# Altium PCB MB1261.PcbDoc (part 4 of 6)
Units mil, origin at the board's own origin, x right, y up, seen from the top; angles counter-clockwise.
Board outline 5119.1 x 2638.79 mil, 6 copper layers (TOP, L2_GND, L3_SIG, L4_VCC, L5_GND, BOTTOM), stack 61 mil thick; 336 components, 316 nets, 1358 pads, 871 vias.
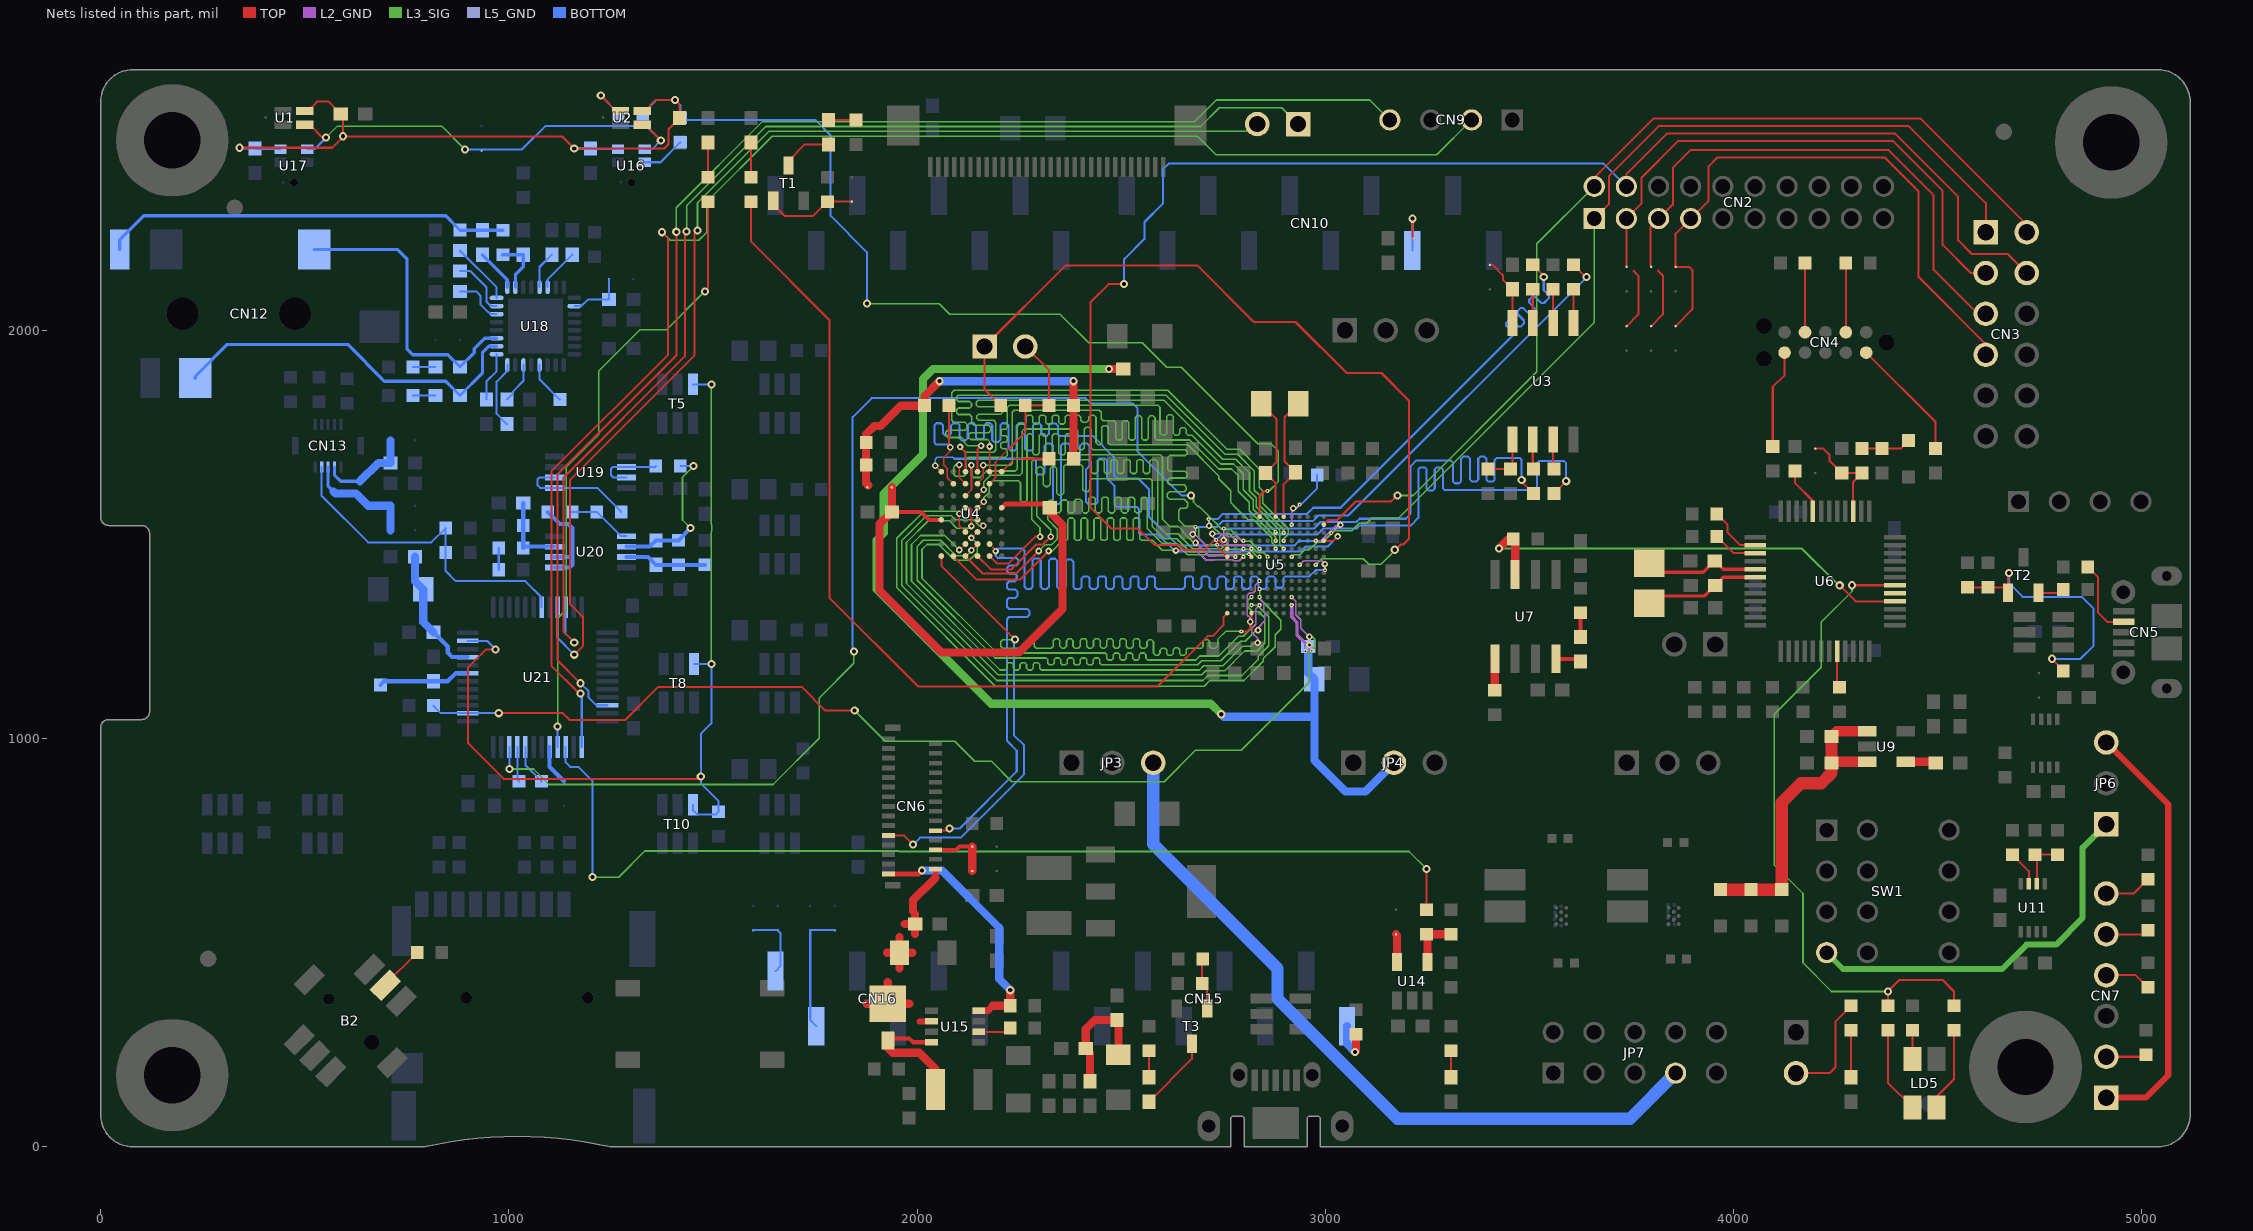
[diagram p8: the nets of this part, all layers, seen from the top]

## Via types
v1: diameter 20, hole 10, TOP to BOTTOM, tented both sides, 317 vias
v2: diameter 24, hole 12, TOP to BOTTOM, tented both sides, 289 vias
v3: diameter 10, hole 4, TOP to L2_GND, tented both sides, 76 vias
v4: diameter 10, hole 4, TOP to L3_SIG, tented both sides, 63 vias
v5: diameter 16, hole 8, L2_GND to L5_GND, tented both sides, 52 vias
v6: diameter 16, hole 8, TOP to BOTTOM, tented both sides, 43 vias
v7: diameter 10, hole 4, L5_GND to BOTTOM, tented both sides, 31 vias

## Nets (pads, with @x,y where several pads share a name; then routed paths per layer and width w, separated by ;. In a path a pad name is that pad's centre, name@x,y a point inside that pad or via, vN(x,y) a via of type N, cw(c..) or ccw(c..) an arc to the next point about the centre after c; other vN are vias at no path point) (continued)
LCD_WE: CN6.20 U4.G5 U5.D7 | length 3052.1
  TOP w4: U4.G5@2177.39,1476.18 2191.55,1462.02 2191.55,1459.25 v6(2192.05,1458.75)
  TOP w5: CN6.20@2044.44,774.27 2074.5,774.27 v1(2079.5,779.27)
  L2_GND w3.5: v3(2937.16,1425) 2947.1,1434.94 2991.06,1434.94 v5(2999,1427)
  L5_GND w3.5: v7(2999,1412) v5(2999,1427)
  BOTTOM w5: v1(2079.5,779.27) 2104.27,779.27 2244,919 2244,970 2220,994 2220,1292.32 2225,1297.32 2270,1297.32 2275,1302.32 2275,1312.32 2270,1317.32 2225,1317.32 2220,1322.32 2220,1339.32 2225,1344.32 2241,1344.32 2246,1349.32 2246,1359.32 2241,1364.32 2225,1364.32 2220,1369.32 2220,1379.32 2225,1384.32 2239,1384.32 2244,1389.32 2244,1399.32 2239,1404.32 2225,1404.32 2220,1409.32 2220,1418 2225,1423 2243,1423 2248,1428 2248,1437 2243,1442 2197.05,1442 2192.05,1447 v6(2192.05,1458.75) 2198.3,1465 2258,1465 2263,1460 2263,1371 2268,1366 2277.75,1366 2282.75,1371 2282.75,1436 2287.75,1441 2297.75,1441 2302.75,1436 2302.75,1371 2307.75,1366 2317.75,1366 2322.75,1371 2322.75,1435 2327.75,1440 2337.75,1440 2342.75,1435 2342.75,1371 2347.75,1366 2357.75,1366 2362.75,1371 2362.75,1433 2367.75,1438 2377.75,1438 2382.75,1433 2382.75,1371 2387.75,1366 2397.75,1366 2402.75,1371 2402.75,1392 2407.75,1397 2417.75,1397 2422.75,1392 2422.75,1371 2427.75,1366 2437.75,1366 2442.75,1371 2442.75,1392 2447.75,1397 2457.75,1397 2462.75,1392 2462.75,1371 2467.75,1366 2477.75,1366 2482.75,1371 2482.75,1392 2487.75,1397 2497.75,1397 2502.75,1392 2502.75,1371 2507.75,1366 2517.75,1366 2522.75,1371 2522.75,1392 2527.75,1397 2537.75,1397 2542.75,1392 2542.75,1371 2547.75,1366 2557.75,1366 2562.75,1371 2562.75,1392 2567.75,1397 2577.75,1397 2582.75,1392 2582.75,1371 2587.75,1366 2651.06,1366 2656.06,1371 2656.06,1392 2661.06,1397 2671.06,1397 2676.06,1392 2676.06,1371 2681.06,1366 2691.06,1366 2696.06,1371 2696.06,1392 2701.06,1397 2711.06,1397 2716.06,1392 2716.06,1371 2721.06,1366 2731.06,1366 2736.06,1371 2736.06,1392 2741.06,1397 2751.06,1397 2756.06,1392 2756.06,1371 2761.06,1366 2771.06,1366 2776.06,1371 2776.06,1392 2781.06,1397 2791.06,1397 2796.06,1392 2796.06,1371 2801.06,1366 2811.06,1366 2816.06,1371 2816.06,1392 2821.06,1397 2831.06,1397 2836.06,1392 2836.06,1371 2841.06,1366 2851.06,1366 2856.06,1371 2856.06,1392 2861.06,1397 2872.34,1397 2877.34,1392 2877.34,1374 2882.34,1369 2892.34,1369 2897.34,1374 2897.34,1392 2902.34,1397 2961,1397 2976,1412 v7(2999,1412)
LED1: R2.1 U5.N13 | length 2201.1
  TOP w5: R2.1@1593.1,2315 1593.1,2216.9 1785,2025 1785,1345 2003,1127 2588.22,1127 2711.72,1250.5 2723.72,1250.5 2750,1276.78 2750,1296.9 U5.N13@2759.99,1306.89
LED_STLINK: R69.1 R71.1 U6.30 | length 1630.4
  TOP w5: v1(4290,1375.16) U6.30@4395.36,1375.16 ; R69.1@4378.1,345 v1(4378.1,380) 4406.1,408 4512,408 4540,380 R71.1@4540,345
  L3_SIG w4: v1(4290,1375.16) 4290,1360 4215,1285 4215,1174 4100,1059 4100,690 4170,620 4170,450 4240,380 v1(4378.1,380)
LEDA: C47.1 C48.1 CN6.28 U15.6 Z1.2 | length 523.8
  TOP w12: 2044.44,658.44 CN6.28@2044.44,679.79
  TOP w15: 2006.3,306.8 U15.6@2035.03,306.8
  TOP w20: 1875.58,350 Z1.2@1928.1,350 ; 1925.98,475 C48.1@1957,475 ; 1928.1,403.02 Z1.2@1928.1,350 ; 1957,436.98 C48.1@1957,475 ; 1957,513.02 C48.1@1957,475 ; 1969.48,545 C47.1@1995,545 ; 1980.62,350 Z1.2@1928.1,350 ; 1988.02,475 C48.1@1957,475 ; 1990,577 1990,604 2044.44,658.44 ; 1995,520.98 C47.1@1995,545 ; 1995,569.02 C47.1@1995,545
LEDK: CN6.29 R67.1 U15.4 | length 616.4
  TOP w12: CN6.29@1930.26,667.98 2003.98,667.98 v1(2012,676)
  TOP w16: U15.4@2151.17,332.39 2172.39,332.39 2185,345
  TOP w20: 2185,345 R67.1@2228.1,345 v1(2228.1,383.1)
  BOTTOM w20: v1(2012,676) 2061,676 2201,536 2201,410.2 v1(2228.1,383.1)
MCO: U6.29
MFX_AGPIO1: R116.1 T5.3 T8.3 T10.3 U21.11 | length 2204.1
  TOP w5: v1(967,1218) 944,1218 900,1174 900,988 987,901 1464,901 v1(1470,907)
  L3_SIG w4: v1(1496,1182.24) 1496,1507.45 1497,1508.45 1497,1522.55 1496,1523.55 v1(1496,1867.24)
  BOTTOM w5: U21.11@898.74,1238.58 946.42,1238.58 v1(967,1218) ; T10.3@1450.5,837.24 1450.5,824.5 1462,813 1506.1,813 R116.1@1513.1,820 1513.1,846.9 1470,890 v1(1470,907) 1470,1011 1496,1037 v1(1496,1182.24) T8.3@1453.6,1182.24 ; T5.3@1450.5,1867.24 v1(1496,1867.24)
MFX_IRQ_OUT: U5.J5 U21.46 | length 2936
  L3_SIG w3.5: 2730,1529 2748,1511 2768,1511 2796,1483 2815.97,1483 2832.16,1466.81 ; 2832.19,1466.81 2834.63,1464.37 v4(2838.73,1464.37)
  L3_SIG w4: v1(1001.1,925) 1060,925 1098,887 1647,887 1760,1000 1760,1099 1845,1184 v1(1845,1213) ; v1(2670.71,1595.11) 2672,1595.11 2677,1590.11 2677,1578.95 2686.95,1569 ; 2687,1569 2688,1568 2691,1568 2730,1529
  BOTTOM w5: v1(1001.1,925) U21.46@1001.1,978.74 ; v1(1845,1213) 1841.88,1216.12 1841.88,1786.88 1888.34,1833.34 2412.29,1833.34 2425,1820.63 2527.63,1820.63 2540.01,1808.25 2540.01,1702.43 2647.33,1595.11 v1(2670.71,1595.11)
MFX_SWCLK: CN9.2 U21.37 | length 3613.2
  TOP w5: v1(1175,1110) 1172,1110 1104,1178 1104,1654 1390,1940 1390,2225 v1(1375,2240)
  L3_SIG w4: v1(1375,2240) 1395,2220 1465,2220 1485,2240 1485,2315 1645,2475 2687,2475 2732,2430 3273.1,2430 CN9.2@3358.1,2515
  BOTTOM w5: v1(1175,1110) 1178.27,1106.73 U21.37@1178.27,978.74
MFX_SWDIO: CN9.4 U21.34 | length 3283.9
  TOP w5: v1(1175,1135) 1119,1191 1119,1647 1410,1938 v1(1410,2241)
  L3_SIG w4: v1(1410,2241) 1410,2300 1621,2511 2680,2511 2733,2564 3109.1,2564 CN9.4@3158.1,2515
  BOTTOM w5: v1(1175,1135) 1195,1115 1195,1100 1213.9,1081.1 U21.34@1241.26,1081.1
MFX_WAKEUP: R109.2 U5.E11 U21.2 | length 2632.4
  TOP w5: v1(975,1061.73) 1132.05,1061.73 1148.78,1045 1285,1045 1366,1126 1717,1126 1775,1068 v1(1847,1068)
  L2_GND w3.5: v3(2917.47,1346.26) 2927.22,1336.51 2927.22,1302.78 2940,1290 2940,1270 v5(2961,1249)
  L3_SIG w3.5: 2959.5,1208.5 2973.75,1222.75 2973.75,1242.94 2967.69,1249 v5(2961,1249)
  L3_SIG w4: v1(1847,1068) 1922,993 2092,993 2141,944 2182,944 2232,894 2605,894 2682,971 2794,971 2959.5,1136.5 2959.5,1208.5
  BOTTOM w5: R109.2@815,1080 833.27,1061.73 U21.2@898.43,1061.73 ; U21.2@898.74,1061.42 U21.2@898.43,1061.73 ; v1(975,1061.73) U21.2@898.43,1061.73
MIC_VDD: C1.1 C2.1 C62.1 C63.1 R78.2 R79.2 U1.1 U2.1 U5.J1 U16.5 U17.5 | length 3993.8
  TOP w5: v1(340,2446.9) 566.9,2446.9 593.1,2473.1 v1(593.1,2475) ; U1.1@499.67,2536.73 506.73,2536.73 530,2560 558.1,2560 C1.1@588.1,2530 593.1,2525 v1(593.1,2475) ; U2.1@1326.36,2536.73 1332.73,2536.73 1360,2564 v1(1407,2564) 1418.1,2552.9 C2.1@1418.1,2520 1391,2492.9 1391,2456 1380,2445 v1(1160,2445) 1130,2475 v1(593.1,2475) ; U5.J1@2838.73,1543.11 2838.73,1593.73 2851,1606 v4(2857.99,1606)
  L3_SIG w3.5: v4(2857.99,1606) 2861.81,1606 v4@2862.71,1606.9
  L3_SIG w4: v1(1877,2065) 2054.06,2065 2080.06,2039 2350.08,2039 2420.08,1969 2551.2,1969 2611.2,1909 2647,1909 2834.01,1721.99 2853.91,1721.99 2866.86,1722 2885,1703.86 2885,1629.19 v4@2862.71,1606.9
  BOTTOM w5: v1(340,2446.9) 341.9,2445 C63.1@378.1,2445 379.4,2443.7 U17.5@440.13,2443.7 ; v1(1160,2445) C62.1@1200,2445 1201.3,2443.7 U16.5@1266.82,2443.7 ; R78.2@1328.1,2530 1362.1,2564 v1(1407,2564) 1420,2551 R79.2@1420,2520 1425,2515 1750,2515 1788,2477 1788,2280 1877,2191 v1(1877,2065)
NETB2_5: B2.5 R60.2 | length 112.3
  TOP w5: B2.5@697.33,394.85 697.33,397.33 R60.2@775,475
NETC4_1: C4.1 SB3.2 U3.8 | length 162.2
  TOP w5: 3410,2160 3435,2135 3435,2123.1 C4.1@3458.1,2100 U3.8@3458.1,2017.72
NETC9_2: C9.2 U5.F1 X1.1 | length 314.1
  TOP w5: U5.F1@2897.79,1543.11 2897.79,1622.69 C9.2@2927.1,1652 2900,1679.1 2900,1786.62 X1.1@2933.38,1820
NETC11_2: C11.2 U5.G1 X1.2 | length 313.9
  TOP w5: X1.2@2842.82,1820 2843,1820 2880,1783 2880,1676.9 C11.2@2853.1,1650 2878.1,1625 U5.G1@2878.1,1543.11
NETC15_1: C15.1 C16.1 SB12.1 U4.D6 U4.E1 | length 1336.5
  TOP w10: C16.1@1938.1,1555 2009,1555 2028.76,1535.24 U4.E1@2059.28,1535.24
  TOP w12: U4.D6@2206.92,1564.76 2216.16,1574 2316,1574 C15.1@2325,1565
  TOP w20: SB12.1@1938.1,1615 C16.1@1938.1,1555 1908.1,1525 1908.1,1361.9 2060,1210 2249,1210 2356,1317 2356,1523 2325,1554 C15.1@2325,1565
NETC33_1: C33.1 C35.1 D2.2 D3.2 D4.2 U9.1 U9.3 | length 787.5
  TOP w25: C35.1@4240,940 4242.6,942.6 U9.3@4327.76,942.6 ; C33.1@4240,1005 4252.4,1017.4 U9.1@4327.76,1017.4
  TOP w30: D2.2@3967.84,629.29 D3.2@4043.1,629.29 D4.2@4118.1,629.29 4118.1,843.1 4165,890 4215,890 4240,915 C35.1@4240,940 C33.1@4240,1005
NETC36_1: C36.1 U9.4 | length 73.8
  TOP w20: U9.4@4422.24,942.6 4492.4,942.6 C36.1@4495,940
NETC55_1: C55.1 C59.1 L5.2 L6.1 | length 306.3
  TOP w20: C59.1@2423.1,160 2423.1,230 L6.1@2413.1,240 2413.1,288.1 2435,310 L5.2@2490,310 2493.1,310 C55.1@2493.1,225
NETC64_1: C64.1 U18.22 | length 104.8
  BOTTOM w5: U18.22@1094.53,2105.28 1094.53,2124.53 C64.1@1155,2185
NETC65_1: C65.1 U18.21 | length 92.2
  BOTTOM w5: U18.21@1074.84,2105.28 1074.84,2154.84 C65.1@1105,2185
NETC66_2: C66.2 R82.2 U18.18 | length 137.7
  BOTTOM w8: R82.2@985,2185 C66.2@1035,2185 1035,2155 1015.79,2135.79 U18.18@1015.79,2105.28
NETC67_1: C67.1 CN12.2 R81.1 R82.1 | length 1001.3
  BOTTOM w8: CN12.2@46.46,2197.48 46.46,2221.46 105,2280 845,2280 R81.1@880,2245 C67.1@935,2245 R82.1@985,2245
NETC67_2: C67.2 U18.17 | length 105
  BOTTOM w8: C67.2@935,2185 996.1,2123.9 U18.17@996.1,2105.28
NETC68_2: C68.2 U18.16 | length 153.3
  BOTTOM w5: C68.2@880,2195 969.72,2105.28 U18.16@969.72,2078.9
NETC69_2: C69.2 U18.15 | length 145.8
  BOTTOM w5: C69.2@880,2145 905,2145 945,2105 945,2070 955.79,2059.21 U18.15@969.72,2059.21
NETC70_2: C70.2 U18.14 | length 125.1
  BOTTOM w5: C70.2@880,2095 920,2095 930,2085 930,2063.78 949.57,2044.21 950,2044.21 954.68,2039.53 U18.14@969.72,2039.53
NETC71_2: C71.2 SB18.2 U18.26 | length 141.3
  BOTTOM w5: U18.26@1160.28,2059.21 1177.33,2059.21 1193.12,2075 C71.2@1245,2075 SB18.2@1245,2125
NETC75_1: C75.1 CN12.6 U18.11 | length 730.5
  BOTTOM w8: CN12.6@522.83,2197.48 727.52,2197.48 750,2175 750,1954 764,1940 850,1940 C75.1@880,1910 915,1945 915,1955 940.47,1980.47 U18.11@969.72,1980.47
NETC75_2: C75.2 R86.1 | length 55
  BOTTOM w5: R86.1@765,1910 C75.2@820,1910
NETC76_1: C76.1 CN12.4 U18.10 | length 905.8
  BOTTOM w8: CN12.4@231.5,1882.52 231.5,1886.5 310,1965 605,1965 695,1875 845,1875 C76.1@880,1840 935,1895 935,1945 950.79,1960.79 U18.10@969.72,1960.79
NETC76_2: C76.2 R90.1 | length 55
  BOTTOM w5: R90.1@765,1840 C76.2@820,1840
NETC78_1: C78.1 U18.8 | length 165.9
  BOTTOM w5: C78.1@995,1770 970,1795 970,1873.78 996.1,1899.88 U18.8@996.1,1914.72
NETC78_2: C78.2 U18.6 | length 101.5
  BOTTOM w5: C78.2@995,1830 1010,1845 1010,1850 1035.47,1875.47 U18.6@1035.47,1914.72
NETC79_2: C79.2 U18.9 | length 121.3
  BOTTOM w5: C79.2@945,1830 945,1875 969.72,1899.72 U18.9@969.72,1941.1
NETC80_1: C80.1 CN13.9 SB20.2 | length 236.5
  BOTTOM w8: CN13.9@572.63,1664.25 572.63,1645 587.63,1630 635,1630
  BOTTOM w20: 635,1630 680,1675 C80.1@710,1675 SB20.2@710,1730
NETC85_2: C85.2 R98.1 R101.2 U20.3 | length 188.2
  BOTTOM w10: C85.2@1035,1576.9 R98.1@1035,1521.9 R101.2@1035,1466.9 1037.8,1469.7 U20.3@1112.01,1469.7
NETC88_1: C88.1 R92.1 R103.1 U20.6 | length 379
  L3_SIG w4: v1(1445,1515) 1425,1535 1425,1640 v1(1451.9,1666.9)
  BOTTOM w5: R92.1@1420,1666.9 v1(1451.9,1666.9)
  BOTTOM w10: U20.6@1287.99,1469.7 1344.7,1469.7 C88.1@1360,1485 R103.1@1415,1485 v1(1445,1515)
NETC88_2: C88.2 R102.2 R103.2 U20.7 | length 199.9
  BOTTOM w10: U20.7@1287.99,1444.1 1340.9,1444.1 C88.2@1360,1425 R103.2@1415,1425 R102.2@1480,1425
NETC91_1: C91.1 C94.1 L8.2 U21.9 | length 321.3
  BOTTOM w10: C94.1@815,1260 850,1225 850,1210 860.79,1199.21 U21.9@898.74,1199.21
  BOTTOM w20: L8.2@770,1445 770,1385 C91.1@790,1365 790,1285 C94.1@815,1260
NETC95_1: C95.1 C100.1 JP4.2 L1.1 U5.E12 | length 2960
  TOP w20: v1(2470,1905) L1.1@2505,1905
  L2_GND w8: v3(2917.47,1326.57) 2917.47,1297.53 2930.25,1284.75 2930.25,1253.75 2955,1229 v5(2961,1229)
  L3_SIG w20: v1(2470,1905) 2039,1905 2014,1880 2014,1695 1918,1599 1918,1503 1901,1486 1901,1365 2181,1085 2719,1085 v1(2745,1059)
  L5_GND w10: v7(2951.26,1213.85) 2954,1216.59 2954,1222 v5(2961,1229) 2967,1223 v7(2967,1215)
  BOTTOM w20: v1(2745,1059) 2751,1053 2973.1,1053 ; C95.1@2958.1,1225 2958.1,1160 C100.1@2973.1,1145 2973.1,1053 ; JP4.2@3168.1,940 3098.1,870 3049,870 2973.1,945.9 2973.1,1053
NETC99_2: C99.2 D6.1 U21.7 | length 225.8
  BOTTOM w10: D6.1@685,1130.71 694.29,1140 C99.2@815,1140 850,1140 869.84,1159.84 U21.7@898.74,1159.84
NETCN4_2: CN4.2 R5.1 | length 170
  TOP w5: CN4.2@4275,1995 R5.1@4275,2165
NETCN4_4: CN4.4 R4.1 | length 170
  TOP w5: CN4.4@4175,1995 R4.1@4175,2165
NETCN4_6: CN4.6 R16.1 | length 242
  TOP w5: R16.1@4096,1715 4096,1861 4125,1890 CN4.6@4125,1945
NETCN4_10: CN4.10 R25.1 | length 305.4
  TOP w5: CN4.10@4325,1945 4495,1775 R25.1@4495,1710
NETCN5_4: CN5.4 R33.2 | length 194.3
  TOP w5: R33.2@4868.1,1420 4893,1395.1 4893,1308 4915.41,1285.59 CN5.4@4955.7,1285.59
NETCN6_24: CN6.24 SB14.2 SB15.2 | length 153.9
  TOP w10: CN6.24@2044.44,727.03 2095.4,727.03 2103.37,735 SB14.2@2135,735
  TOP w20: SB15.2@2135,675 SB14.2@2135,735
NETCN7_1: CN7.1 JP6.3 | length 1052.6
  TOP w15: CN7.1@4913.1,120 5010,120 5065,175 5065,838.1 JP6.3@4913.1,990
NETCN7_2: CN7.2 R66.1 | length 99
  TOP w5: CN7.2@4913.1,220 5005,220 R66.1@5010,225
NETCN7_4: CN7.4 R63.1 | length 114.3
  TOP w5: CN7.4@4913.1,420 4985,420 R63.1@5015,390
NETCN7_5: CN7.5 R59.1 | length 106
  TOP w5: CN7.5@4913.1,520 5005,520 R59.1@5015,530
NETCN7_6: CN7.6 R56.1 | length 116.4
  TOP w5: CN7.6@4913.1,620 4980,620 R56.1@5015,655
NETCN10_8: CN10.8 SB2.1 | length 128.3
  TOP w5: v1(3213.1,2273.1) 3213.1,2230 SB2.1@3218.1,2225
  BOTTOM w5: CN10.8@3213.1,2195 v1(3213.1,2273.1)
NETCN13_7: CN13.7 R99.1 R104.1 U21.19 | length 826.5
  BOTTOM w5: CN13.7@541.13,1664.25 541.13,1593.87 655,1480 810,1480 R99.1@845,1515 R104.1@845,1455 845,1410 870,1385 1040,1385 1079.84,1345.16 U21.19@1079.84,1321.26
NETCN13_8: CN13.8 SB21.1 SB22.2 | length 279.2
  BOTTOM w8: CN13.8@556.88,1664.25 556.88,1618.12 570,1605
  BOTTOM w20: 570,1605 575,1600 625,1600 655,1570 SB21.1@710,1570 SB22.2@710,1510
NETCN15_1: CN15.1 R72.2 | length 115.1
  TOP w20: v1(3073,232) 3075,234 R72.2@3075,275
  BOTTOM w20: CN15.1@3053.1,295 3053.1,251.9 v1(3073,232)
NETCN16_5: CN16.5 SB25.2 SB26.2 | length 301.2
  BOTTOM w5: CN16.5@1753.1,295 1738.1,310 SB26.2@1738.1,530 SB25.2@1798.1,530
NETCN16_6: CN16.6 SB27.2 SB28.2 | length 167.8
  BOTTOM w5: SB28.2@1598.1,530 SB27.2@1658.1,530 1665,523.1 1665,441.9 CN16.6@1653.1,430
NETD1_2: D1.2 R23.2 R24.1 | length 122.1
  TOP w5: R23.2@4315,1710 R24.1@4364.1,1710 4409.81,1710 D1.2@4429.1,1729.29
NETJP1_1: JP1.1 U21.22 | length 2914.5
  TOP w5: v1(1160,1235) 1134,1261 1134,1639 1431,1936 1431,2237.74 v1(1435.26,2242)
  L3_SIG w4: v1(1435.26,2242) 1435.26,2305.26 1629,2499 2694,2499 2740,2545 2893.1,2545 JP1.1@2933.1,2505
  BOTTOM w5: U21.22@1138.9,1321.26 1138.9,1256.1 v1(1160,1235)
NETJP1_2: JP1.2 U21.21 | length 2842.8
  TOP w5: v1(1160,1205) 1181,1226 1181,1298 1149,1330 1149,1632.79 1454,1937.79 1454,2236 v1(1462,2244)
  L3_SIG w4: v1(1462,2244) 1462,2312 1637,2487 2815.1,2487 JP1.2@2833.1,2505
  BOTTOM w5: U21.21@1119.21,1321.26 1119.21,1245.79 v1(1160,1205)
NETJP3_3: JP3.3 JP7.7 | length 1847.6
  BOTTOM w30: JP3.3@2578.1,940 2578.1,740.9 2883,436 2883,362 3177,68 3746.1,68 JP7.7@3858.1,180
NETJP6_1: JP6.1 SW1.4 | length 949.3
  L3_SIG w15: SW1.4@4228.1,475 4268.1,435 4658,435 4718,495 4790,495 4855,560 4855,731.9 JP6.1@4913.1,790
NETJP8_2: JP8.2 R68.2 | length 268.9
  TOP w5: JP8.2@4153.1,180 4235,180 4250,195 4250,306.9 R68.2@4288.1,345
NETJP9_2: JP9.2 R12.1 R14.1 U4.B5 | length 454.6
  TOP w4: U4.B5@2177.39,1623.82 2192,1638.43 2192,1677 2225,1710
  TOP w5: 2225,1710 2265,1750 R12.1@2265,1815 R14.1@2323.1,1815 2323.1,1901.9 JP9.2@2265,1960
NETL7_2: L7.2 U15.8 Z1.1 | length 319.4
  TOP w10: Z1.1@1928.1,260 1933.1,265 1980,265 1989.39,255.61 U15.8@2035.03,255.61
  TOP w20: Z1.1@1928.1,260 1928.1,241.9 1940,230 2005,230 2045.1,189.9 L7.2@2045.1,140
NETLD1_2: LD1.2 R1.2 | length 85
  TOP w5: R1.2@1488.1,2375 LD1.2@1488.1,2460
NETLD2_2: LD2.2 R2.2 | length 85
  TOP w5: R2.2@1593.1,2375 LD2.2@1593.1,2460
NETLD3_1: LD3.1 R123.2 | length 66.9
  TOP w5: LD3.1@1783.1,2515 R123.2@1850,2515
NETLD3_2: LD3.2 T1.3 | length 126.4
  TOP w5: T1.3@1685,2403.31 1685,2415 1725,2455 LD3.2@1783.1,2455
NETLD4_1: LD4.1 R36.1 | length 60
  TOP w10: LD4.1@3625,1248.1 R36.1@3625,1308.1
NETLD4_2: LD4.2 U7.8 | length 62.8
  TOP w10: U7.8@3565,1194.8 3618.3,1194.8 LD4.2@3625,1188.1
NETLD5_2: LD5.2 R71.2 | length 206.6
  TOP w5: LD5.2@4497.63,95.94 4497.63,122.63 4540,165 R71.2@4540,285
NETLD5_3: LD5.3 R69.2 | length 214.1
  TOP w5: R69.2@4378.1,285 4378.1,156.41 LD5.3@4438.57,95.94
NETLD5_4: LD5.4 R70.2 | length 71.1
  TOP w5: R70.2@4438.1,285 4438.57,284.53 LD5.4@4438.57,214.06
NETLD6_1: LD6.1 R74.2 | length 65
  TOP w5: LD6.1@2568.1,170 R74.2@2568.1,235
NETLD6_2: LD6.2 T3.3 | length 185.2
  TOP w5: LD6.2@2568.1,110 2673.1,215 T3.3@2673.1,251.69
NETLD7_1: LD7.1 R75.2 | length 65
  TOP w5: LD7.1@3308.1,170 R75.2@3308.1,235
NETLD8_1: LD8.1 R68.1 | length 115
  TOP w5: LD8.1@4288.1,170 R68.1@4288.1,285
NETR1_1: R1.1 U21.40 | length 1527.1
  TOP w5: v1(1480,2095) 1488.1,2103.1 R1.1@1488.1,2315
  L3_SIG w4: v1(1119.21,1029.21) 1119.21,1294.21 1140,1315 1140,1665 1220,1745 1220,1900 1321,2001 1386,2001 v1(1480,2095)
  BOTTOM w5: U21.40@1119.21,978.74 v1(1119.21,1029.21)
NETR6_2: R6.2 U3.7 | length 82.3
  TOP w5: U3.7@3508.1,2017.72 R6.2@3508.1,2100
NETR7_2: R7.2 U3.6 | length 82.3
  TOP w5: U3.6@3558.1,2017.72 R7.2@3558.1,2100
NETR8_2: R8.2 U3.5 | length 82.3
  TOP w5: U3.5@3608.1,2017.72 R8.2@3608.1,2100
NETR15_2: R15.2 U4.A6 | length 129.3
  TOP w4: U4.A6@2206.92,1653.35 2238.57,1685 2260,1685
  TOP w5: 2260,1685 R15.2@2323.1,1685
NETR17_1: R17.1 U6.44 | length 117.2
  TOP w5: R17.1@4150,1655 4150,1626 4194.57,1581.43 U6.44@4194.57,1556.26
NETR22_2: R22.2 R23.1 SB11.2 U6.39 | length 251.5
  TOP w5: SB11.2@4200,1710 4220,1710 4235,1695 4235,1680 R22.2@4265,1650 R23.1@4315,1650 4293,1628 U6.39@4293,1556.26
NETR26_2: R26.2 R27.1 U3.1 | length 129.4
  TOP w5: R26.2@3398.1,1660 R27.1@3453.1,1660 3458.1,1665 U3.1@3458.1,1732.28
NETR28_2: R28.2 U3.2 | length 73.1
  TOP w5: U3.2@3508.1,1732.28 3508.1,1661.9 R28.2@3510,1660
NETR29_2: R29.2 U3.3 | length 73.1
  TOP w5: U3.3@3558.1,1732.28 3558.1,1661.9 R29.2@3560,1660
NETR30_2: R30.2 U6.2 | length 136.6
  TOP w5: R30.2@3959.1,1550 3985,1524.1 3985,1505 4016.42,1473.58 U6.2@4052.84,1473.58
NETR31_2: R31.2 U6.3 | length 110.8
  TOP w5: R31.2@3959.1,1495 4000.2,1453.9 U6.3@4052.84,1453.9
NETR34_1: R34.1 R35.1 R44.2 T2.1 | length 659.9
  TOP w5: R34.1@4573.1,1370 R35.1@4623.1,1370 4659.29,1370 T2.1@4672.6,1356.69 4672.6,1402.6 v1(4675,1405) ; v1(4780,1195) 4808.1,1166.9 R44.2@4808.1,1165
  BOTTOM w5: v1(4675,1405) 4675,1380 4708.5,1346.5 4853.5,1346.5 4882,1318 4882,1227 4850,1195 v1(4780,1195)
NETR37_1: R37.1 T2.2 | length 64.1
  TOP w4.8: R37.1@4799.79,1356.69 R37.1@4808.1,1365
  TOP w5: T2.2@4747.4,1356.69 R37.1@4799.79,1356.69
NETR48_2: R48.2 U6.20 | length 91.4
  TOP w5: U6.20@4253.63,1213.74 4253.63,1131.37 R48.2@4260,1125
NETR50_2: R50.2 U7.5 | length 76.7
  TOP w20: R50.2@3415,1118.1 U7.5@3415,1194.8
NETR53_1: R53.1 U11.3 | length 87.6
  TOP w5: R53.1@4683.1,715 4723.26,674.84 U11.3@4723.26,644.06
NETR54_1: R54.1 R55.2 U11.2 | length 127.9
  TOP w5: U11.2@4742.94,644.06 4742.94,710.16 R54.1@4738.1,715 R55.2@4793.1,715
NETR57_1: R57.1 R58.2 U14.4 | length 128.8
  TOP w20: U14.4@3250.5,452.24 3250.5,517.6 R57.1@3248.1,520 R58.2@3308.1,520
NETR57_2: R57.2 U21.39 | length 2545.8
  TOP w5: R57.2@3248.1,580 v1(3248.1,680)
  L3_SIG w4: v1(1205,660) 1268.96,660 1332.96,724 1954.92,724 1956.02,722.9 2014.88,722.9 2014.98,723 3205.1,723 v1(3248.1,680)
  BOTTOM w5: U21.39@1138.9,978.74 1138.9,941.1 1150,930 1170,930 1205,895 v1(1205,660)
NETR62_2: R62.2 R65.2 T3.1 | length 127.6
  TOP w5: R62.2@2700,460 2698.1,458.1 R65.2@2698.1,400 2710.5,387.6 T3.1@2710.5,338.31
NETR73_1: R73.1 U15.2 | length 80.6
  TOP w5: U15.2@2151.17,281.2 2219.3,281.2 R73.1@2228.1,290
NETR78_1: R78.1 U2.2 | length 126.9
  TOP w5: v1(1225,2575) 1263.27,2536.73 U2.2@1273.22,2536.73
  BOTTOM w5: v1(1225,2575) 1268.1,2531.9 R78.1@1268.1,2530
NETR79_1: R79.1 U16.2 | length 107.4
  BOTTOM w5: U16.2@1332.76,2411.34 1371.34,2411.34 R79.1@1420,2460
NETR91_2: R91.2 U18.4 | length 105.6
  BOTTOM w5: U18.4@1074.84,1914.72 1074.84,1879.94 1124.78,1830 R91.2@1125,1830
NETR92_2: R92.2 U19.6 U19.7 | length 168.3
  BOTTOM w5: U19.7@1287.99,1639.1 1255.9,1639.1 1250,1645 1250,1660 1254.7,1664.7 U19.6@1287.99,1664.7 1357.8,1664.7 R92.2@1360,1666.9
NETR93_1: R93.1 U5.E2 | length 152.9
  L2_GND w3.5: v3(2917.47,1523.43) 2917.47,1559.47 2921.37,1563.37 v5(2921.37,1563.64)
  L5_GND w3.5: v5(2921.37,1563.64) 2928.14,1563.64 v7(2937.05,1572.5)
  BOTTOM w5: v7(2937.05,1572.5) 2939.5,1572.5 2980,1613 R93.1@2980,1645
NETR96_1: R96.1 R97.1 U20.5 | length 157.7
  BOTTOM w5: R97.1@1155,1555 R96.1@1215,1555 1274.71,1495.29 U20.5@1287.99,1495.29
NETR96_2: R96.2 U19.1 U19.2 | length 290.6
  BOTTOM w5: U19.2@1112.01,1639.1 1074.1,1639.1 1070,1635 1070,1620 1076.49,1613.51 U19.1@1112.01,1613.51 1216.49,1613.51 R96.2@1275,1555
NETR97_2: R97.2 U20.1 U20.2 | length 256.9
  BOTTOM w10: R97.2@1095,1555 1125,1525 1145,1525 1155,1515 1155,1440 ; U20.1@1112.01,1418.51 1148.51,1418.51 1155,1425 1155,1440 ; U20.2@1112.01,1444.1 1150.9,1444.1 1155,1440
NETR101_1: R101.1 R105.1 | length 53.8
  BOTTOM w5: R105.1@975,1413.1 R101.1@975,1466.9
NETR112_1: R112.1 U21.44 | length 100.1
  BOTTOM w5: U21.44@1040.47,978.74 1040.47,934.53 R112.1@1080,895
NETR113_1: R113.1 U21.45 | length 85.5
  BOTTOM w5: U21.45@1020.79,978.74 1020.79,899.21 R113.1@1025,895
NETR124_1: R124.1 SB1.1 T1.1 | length 227.5
  TOP w5: T1.1@1647.6,2316.69 1647.6,2307.4 1675,2280 1745,2280 R124.1@1780,2315 SB1.1@1840,2315
NETSB16_2: SB16.2 U14.5 | length 68.8
  TOP w20: SB16.2@3173.1,520 3175.7,517.4 U14.5@3175.7,452.24
NETSB17_1: SB17.1 U1.4 U2.4 U16.1 U17.1 | length 1125.8
  TOP w5: U1.4@499.67,2503.27 511.73,2503.27 543,2472 v1(552,2472) ; U2.4@1326.36,2503.27 1333.73,2503.27 v1(1372,2465)
  L3_SIG w4: v1(552,2472) 580,2500 835,2500 v1(892,2443)
  BOTTOM w5: U17.1@506.07,2443.7 523.7,2443.7 v1(552,2472) ; v1(892,2443) 1032,2443 1089,2500 1337,2500 v1(1372,2465) 1350.7,2443.7 U16.1@1332.76,2443.7
NETSB24_2: SB24.2 U21.41 | length 98.4
  BOTTOM w10: U21.41@1099.53,978.74 1099.53,930.47 SB24.2@1135,895
OSC_IN: C20.2 U6.5 X2.2 | length 289.1
  TOP w8: X2.2@3793,1429.21 3815.21,1407 3926.1,1407 C20.2@3954.1,1435 3974.57,1414.53 U6.5@4052.84,1414.53
OSC_OUT: C23.2 U6.6 X2.1 | length 286.4
  TOP w8: X2.1@3793,1330.79 3811.21,1349 3929,1349 C23.2@3955,1375 3974.84,1394.84 U6.6@4052.84,1394.84
PMOD#1: CN2.1 CN3.1 U5.E6 | length 2476.2
  TOP w5: CN2.1@3658.77,2273.42 3695,2309.65 3695,2378 3817,2500 4429,2500 4618.1,2310.9 CN3.1@4618.1,2240
  L3_SIG w3.5: v4(2917.47,1444.69) 2923.06,1450.28 2936.45,1450.28 2936.61,1450.44 2937.44,1450.44 2949,1462 2961,1462 2980,1481 2994,1481 3022,1509 3065,1509 3083,1527 3101.73,1527 3109.71,1534.98
  L3_SIG w4: 3109.71,1534.98 3113.73,1539 3179,1539 3658.77,2018.77 CN2.1@3658.77,2273.42
PMOD#2: CN2.2 CN3.2 SB4.2 SB7.2 | length 1479.2
  TOP w5: SB7.2@3738.1,2010 3767,2038.9 3767,2133 3755,2145 ; SB4.2@3738.1,2155 3738.1,2272.83 CN2.2@3737.51,2273.42 3775,2310.91 3775,2374 3865,2464 4390,2464 4512,2342 4512,2209 4581,2140 CN3.2@4618.1,2140
PMOD#3: CN2.3 CN3.3 SB5.2 SB8.2 | length 1473.5
  TOP w5: 3797,2158 3797,2254.17 CN2.3@3816.25,2273.42 3852,2309.17 3852,2399 3894,2441 4380,2441 4490,2331 4490,2148 4598,2040 CN3.3@4618.1,2040 ; SB8.2@3798.1,2010 3827,2038.9 3827,2134 3815,2146
PMOD#4: CN2.4 CN3.4 SB6.2 SB9.2 | length 1504.1
  TOP w5: SB9.2@3858.1,2010 3899,2050.9 3899,2147 3891,2155 SB6.2@3858.1,2155 3858.1,2236.53 CN2.4@3894.99,2273.42 3939,2317.43 3939,2402 3960,2423 4370,2423 4453,2340 4453,2131 4618.1,1965.9 CN3.4@4618.1,1940
PMOD#11: CN2.11 CN3.7 U5.A2 | length 2456.6
  TOP w5: U5.A2@2996.21,1523.43 3007.77,1534.99 3029.48,1534.99 3074.99,1580.5 3161,1580.5 3175.5,1595 v1(3177,1595) ; CN2.11@3658.77,2352.16 3658.77,2373.77 3804,2519 4457,2519 4718.1,2257.9 CN3.7@4718.1,2240
  L3_SIG w4: v1(3177,1595) 3215,1595 3518,1898 3518,2211.39 CN2.11@3658.77,2352.16
PMOD#12: CN2.12 CN3.8 U5.N5 | length 3741.3
  TOP w5: v1(2507,2113) 2469,2113 2425,2069 2425,1627.03 2424.5,1626.53 2424.5,1595.47 2425,1594.97 2425,1565 2476,1514 2541,1514 2581.66,1473.34 2642.66,1473.34 2654,1462 2705,1462 2728.25,1485.25 2739.11,1485.25 U5.N5@2759.99,1464.37 ; CN2.12@3737.51,2352.16 3737.51,2381.51 3838,2482 4395,2482 4550,2327 4550,2220 4583,2187 4671.1,2187 CN3.8@4718.1,2140
  BOTTOM w5: v1(2507,2113) 2507,2174 2557,2224 2557,2265 2602,2310 2602,2394 2616,2408 3681.67,2408 CN2.12@3737.51,2352.16
PSRAM_A0: U4.A3 U5.F5 | length 1400.1
  TOP w4: v6@2109,1710 2118.34,1700.66 U4.A3@2118.34,1653.35
  TOP w5: v6(2105,1714) v6@2109,1710
  L3_SIG w3.5: 2814.1,1606.9 2831,1590 2831,1567.04 2888,1510.04 2888,1474.16 v4(2897.79,1464.37)
  L3_SIG w4: v6(2105,1714) 2118,1701 2187.39,1701 2192.39,1706 2192.39,1774 2187.39,1779 2150.39,1779 2146,1783.39 2146,1789.61 2150.39,1794 2204,1794 2209,1799 2209,1807 2204,1812 2149.69,1812 2145,1816.69 2145,1823.31 2149.69,1828 2604.94,1828 2748.94,1684 2780.16,1684 2814,1650.16 2814,1607 2814.1,1606.9
PSRAM_A1: U4.A4 U5.F4 | length 1396.4
  TOP w4: U4.A4@2147.86,1653.35 2147.86,1708.44 2149.42,1710
  TOP w5: 2149.42,1710 v6(2156.49,1717.07)
  L3_SIG w3.5: 2845.99,1606.9 2846.5,1606.39 2846.5,1576.5 2909,1514 2909,1499.99 2897.79,1488.78 v4(2897.79,1484.06)
  L3_SIG w4: v6(2156.49,1717.07) 2123.15,1717.07 2115.61,1724.61 2115.61,1731.02 2109.63,1737 2075,1737 2070,1742 2070,1750 2075,1755 2117.37,1755 2122.37,1760 2122.37,1769.02 2117.39,1774 2090,1774 2085,1779 2085,1847 2091,1853 2613.9,1853 2758.9,1708 2790.12,1708 2838,1660.12 2838,1614.89 2845.99,1606.9
PSRAM_A2: U4.A5 U5.F3 | length 1400.6
  TOP w4: U4.A5@2177.39,1653.35 v6@2177.39,1710
  TOP w5: v6@2177.39,1710 v6(2177.39,1715)
  L3_SIG w3.5: 2827.1,1606.9 2839,1595 2839,1570 2897.79,1511.21 v4(2897.79,1503.74)
  L3_SIG w4: v6(2177.39,1715) 2177.39,1727.07 2172.39,1732.07 2130.96,1732.07 2126,1737.03 2126,1744.04 2130.96,1749 2175.39,1749 2180.39,1754 2180.39,1762 2175.39,1767 2139,1767 2134,1772 2134,1788.27 2129,1793.27 2101,1793.27 2097,1797.27 2097,1805.27 2101,1809.27 2128.31,1809.27 2133,1813.96 2133,1820.58 2128.31,1825.27 2101,1825.27 2097,1829.27 2097,1837 2101,1841 2608.92,1841 2753.92,1696 2785.14,1696 2826,1655.14 2826,1611.98 2826.11,1611.87 2826.11,1607.89 2827.1,1606.9
PSRAM_A3: U4.B3 U5.G3 | length 1404.8
  TOP w3.5: U5.G3@2878.1,1503.74 2878.1,1504.1 2878.25,1504.25 v4(2878.25,1506)
  TOP w4: v6(2103,1670) 2103,1639.16 U4.B3@2118.34,1623.82
  L3_SIG w3.5: 2801.6,1606.9 2801.6,1606.4 2823,1585 2823,1561.25 v4(2878.25,1506)
  L3_SIG w4: v6(2103,1670) 2094.8,1670 2089.8,1665 2089.8,1647 2094.8,1642 2114.05,1642 2119.05,1647 2119.05,1683 2124.05,1688 2216,1688 2221,1693 2221,1705.43 2217,1709.43 2209,1709.43 2205,1713.43 2205,1721.43 2209,1725.43 2217,1725.43 2221,1729.43 2221,1737.43 2217,1741.43 2209,1741.43 2205,1745.43 2205,1753.43 2209,1757.43 2217,1757.43 2221,1761.43 2221,1811 2226,1816 2590,1816 2595,1811 2595,1748 2600,1743 2607.44,1743 2611.44,1747 2611.44,1788.52 2616.13,1793.21 2622.75,1793.21 2627.44,1788.52 2627.44,1747 2631.44,1743 2639.44,1743 2643.44,1747 2643.44,1756.52 2648.13,1761.21 2654.75,1761.21 2659.44,1756.52 2659.44,1747 2663.44,1743 2672.96,1743 2743.96,1672 2775.18,1672 2799,1648.18 2799,1609.5 2801.6,1606.9
PSRAM_A4: U4.B4 U5.G4 | length 1401.1
  TOP w4: U4.B4@2147.86,1623.82 2147.86,1624.86 2162,1639 v6(2162,1669)
  L3_SIG w3.5: 2787.86,1604.55 2813.54,1578.87 2813.54,1557.46 2868.5,1502.5 2868.5,1501.96 2878.1,1492.36 v4(2878.1,1484.06)
  L3_SIG w4: v6(2162,1669) 2228,1669 2233,1674 2233,1799 2238,1804 2446,1804 2451,1799 2451,1783 2456,1778 2482.51,1778 2486.51,1774 2486.51,1735 2490.51,1731 2498.51,1731 2502.51,1735 2502.51,1774 2506.51,1778 2514.51,1778 2518.51,1774 2518.51,1735 2522.51,1731 2530.51,1731 2534.51,1735 2534.51,1785.31 2539.2,1790 2545.82,1790 2550.51,1785.31 2550.51,1735 2554.51,1731 2562.51,1731 2566.51,1735 2566.51,1785.31 2571.2,1790 2577.82,1790 2582.51,1785.31 2582.51,1735 2586.51,1731 2667.98,1731 2738.98,1660 2770.2,1660 2787,1643.2 2787,1605.4 2787.85,1604.55
PSRAM_A5: U4.C3 U5.G5 | length 1402.7
  TOP w4: U4.C3@2118.34,1594.29 2133.05,1609 v6(2133.05,1669.05)
  L3_SIG w3.5: 2776,1570 2811,1535 2824.7,1535 2868.35,1491.35 2868.35,1480.02 2878.1,1470.27 v4(2878.1,1464.37)
  L3_SIG w4: v6(2133.05,1669.05) 2133.05,1644 2138.05,1639 2154,1639 2170,1655 2240,1655 2245,1660 2245,1765 2250,1770 2262.93,1770 2266.93,1774 2266.93,1788 2270.93,1792 2278.93,1792 2282.93,1788 2282.93,1774 2286.93,1770 2294.93,1770 2298.93,1774 2298.93,1788 2302.93,1792 2310.93,1792 2314.93,1788 2314.93,1774 2318.93,1770 2326.93,1770 2330.93,1774 2330.93,1788 2334.93,1792 2342.93,1792 2346.93,1788 2346.93,1774 2350.93,1770 2358.93,1770 2362.93,1774 2362.93,1788 2366.93,1792 2396,1792 2401,1787 2401,1779 2406,1774 2415,1774 2420,1779 2420,1787 2425,1792 2433,1792 2438,1787 2438,1724 2443,1719 2448.42,1719 2452.42,1723 2452.42,1762 2456.42,1766 2464.42,1766 2468.42,1762 2468.42,1723 2472.42,1719 2663,1719 2739,1643 2739,1636 2768.17,1606.83 2768.17,1577.83 2776,1570
PSRAM_A6: U4.C4 U5.N6 | length 1403.5
  TOP w4: U4.C4@2147.86,1594.29 2162.57,1609 v6(2163,1609)
  TOP w5: v4(2734.75,1474.75) 2734.75,1469.93 U5.N6@2759.99,1444.69
  L3_SIG w3.5: 2688.8,1514.2 2689,1514.2 2690,1513.2 2690,1490 2705.25,1474.75 v4(2734.75,1474.75)
  L3_SIG w4: v6(2163,1609) 2163,1628 2180,1645 2252,1645 2257,1650 2257,1753 2262,1758 2389.38,1758 2393.38,1754 2393.38,1711.69 2398.07,1707 2404.69,1707 2409.38,1711.69 2409.38,1757.13 2414.25,1762 2421.13,1762 2426,1757.13 2426,1712 2431,1707 2657,1707 2662,1702 2662,1698 2657,1693 2619,1693 2614,1688 2614,1659 2619,1654 2657,1654 2662,1649 2662,1643 2657,1638 2619,1638 2614,1633 2614,1626 2619,1621 2654,1621 2659,1616 2659,1609 2654,1604 2618,1604 2613,1599 2613,1591 2618,1586 2654,1586 2663,1577 2663,1569 2658,1564 2646,1564 2641,1559 2641,1535 2656,1520 2683,1520 2688.8,1514.2
PSRAM_A7: U4.D4 U5.M6 | length 1400.2
  TOP w4: U4.D4@2147.86,1564.76 v6(2163,1579.9)
  L2_GND w3.5: 2730,1446.79 2777.57,1446.79 v3(2779.67,1444.69)
  L2_GND w5: v5(2682,1479) 2683,1479 2715.21,1446.79 2730,1446.79
  L3_SIG w4: v6(2163,1579.9) 2163,1589.2 2177,1603.2 2177,1622 2186,1631 2248,1631 2253,1626 2253,1583.69 2257.69,1579 2264.31,1579 2269,1583.69 2269,1741.88 2273.12,1746 2278.96,1746 2283.08,1741.88 2283.08,1699 2287.08,1695 2295.08,1695 2299.08,1699 2299.08,1741.31 2303.77,1746 2310.39,1746 2315.08,1741.31 2315.08,1699 2319.08,1695 2327.08,1695 2331.08,1699 2331.08,1741.31 2335.77,1746 2342.39,1746 2347.08,1741.31 2347.08,1699 2351.08,1695 2359.08,1695 2363.08,1699 2363.08,1741.31 2367.77,1746 2374.39,1746 2379.08,1741.31 2379.08,1699 2383.08,1695 2596,1695 2601,1690 2601,1537.12 2619.12,1519 2640,1519 2652.25,1506.75 2652.25,1504.36 2677.61,1479 v5(2682,1479)
PSRAM_A8: U4.H2 U5.L6 | length 1402.7
  TOP w5: U4.H2@2088.81,1446.65 2146.46,1389 2252,1389 v6(2322,1459)
  L2_GND w3.5: 2728.3,1437.2 2773.37,1437.2 2775.63,1434.94 2789.62,1434.94 v3(2799.36,1444.68)
  L2_GND w5: v5(2634,1460) 2684,1460 2706.8,1437.2 2728.3,1437.2
  L3_SIG w3.5: 2617.1,1460.9 2633.1,1460.9 v5(2634,1460)
  L3_SIG w4: v6(2322,1459) 2331,1459 2357,1485 2365.34,1485 2369.34,1489 2369.34,1536 2373.34,1540 2381.34,1540 2385.34,1536 2385.34,1489 2389.34,1485 2397.34,1485 2401.34,1489 2401.34,1536 2405.34,1540 2413.34,1540 2417.34,1536 2417.34,1489 2421.34,1485 2429.34,1485 2433.34,1489 2433.34,1536 2437.34,1540 2445.34,1540 2449.34,1536 2449.34,1489 2453.34,1485 2461.34,1485 2465.34,1489 2465.34,1536 2469.34,1540 2477.34,1540 2481.34,1536 2481.34,1489 2485.34,1485 2493.34,1485 2497.34,1489 2497.34,1536 2501.34,1540 2509.34,1540 2513.34,1536 2513.34,1489 2517.34,1485 2525.34,1485 2529.34,1489 2529.34,1536 2533.34,1540 2541.34,1540 2545.34,1536 2545.34,1489 2549.34,1485 2576,1485 2600.1,1460.9 2617.1,1460.9
PSRAM_A9: U4.H3 U5.K6 | length 1420.2
  TOP w3.5: v4(2812.43,1451.3) U5.K6@2819.04,1444.69
  TOP w5: U4.H3@2118.34,1446.65 2160.99,1404 2243,1404 v6(2298,1459)
  L3_SIG w3.5: 2622.75,1477.25 2635.75,1477.25 2663,1450 2755,1450 2756.3,1451.3 v4(2812.43,1451.3)
  L3_SIG w4: v6(2298,1459) 2313,1474 2329,1474 2343.5,1488.5 2343.5,1512.5 2320,1536 2320,1578.18 2324.82,1583 2331.63,1583 2336.45,1578.18 2336.45,1557.69 2341.14,1553 2347.76,1553 2352.45,1557.69 2352.45,1579 2357.45,1584 2364.59,1584 2369.59,1579 2369.59,1556 2373.59,1552 2381.59,1552 2385.59,1556 2385.59,1582 2389.59,1586 2399,1586 2404,1581 2404,1556.79 2408.79,1552 2415.57,1552 2420.36,1556.79 2420.36,1587 2424.36,1591 2432.36,1591 2436.36,1587 2436.36,1556.69 2441.05,1552 2447.67,1552 2452.36,1556.69 2452.36,1587 2456.36,1591 2464.36,1591 2468.36,1587 2468.36,1556.69 2473.05,1552 2479.67,1552 2484.36,1556.69 2484.36,1587 2488.36,1591 2496.36,1591 2500.36,1587 2500.36,1556.69 2505.05,1552 2511.67,1552 2516.36,1556.69 2516.36,1587 2520.36,1591 2528,1591 2533,1586 2533,1556.69 2537.69,1552 2544.31,1552 2549,1556.69 2549,1586 2554,1591 2559,1591 2564,1586 2564,1513.98 2600.73,1477.25 2622.75,1477.25
PSRAM_A10: U4.H4 U5.J6 | length 1409.7
  TOP w5: U4.H4@2147.86,1446.65 2180.51,1414 2231,1414 2292,1475 2308,1475 v6(2327,1494)
  L3_SIG w3.5: 2634.75,1489.25 2635.75,1489.25 2667.5,1457.5 2748.5,1457.5 2754,1463 2814.75,1463 2833.06,1444.69 v4(2838.73,1444.69)
  L3_SIG w4: v6(2327,1494) 2327,1511 2293,1545 2293,1660.31 2297.69,1665 2304.31,1665 2309,1660.31 2309,1621.98 2313.98,1617 2321.02,1617 2326,1621.98 2326,1661.31 2330.69,1666 2337.31,1666 2342,1661.31 2342,1601 2347,1596 2354,1596 2359,1601 2359,1666 2364,1671 2401,1671 2406,1666 2406,1609 2411,1604 2418,1604 2423,1609 2423,1631 2428,1636 2571,1636 2576,1631 2576,1518.96 2605.71,1489.25 2634.75,1489.25
PSRAM_A11: U4.H5 U5.H6 | length 1421.3
  TOP w5: U4.H5@2177.39,1446.65 2196.04,1428 2223,1428 2289,1494 v6(2301,1494)
  L3_SIG w3.5: 2643.24,1497.74 2643.24,1496.52 2674.76,1465 2745.39,1465 2754.39,1474 2814.36,1474 2833.92,1454.44 2848.66,1454.44 v4(2858.41,1444.69)
  L3_SIG w4: v6(2301,1494) 2301,1516 2281,1536 2281,1678 2286,1683 2422.1,1683 2426.1,1679 2426.1,1653 2430.1,1649 2438.1,1649 2442.1,1653 2442.1,1679 2446.1,1683 2454.1,1683 2458.1,1679 2458.1,1653 2462.1,1649 2470.1,1649 2474.1,1653 2474.1,1679 2478.1,1683 2486.1,1683 2490.1,1679 2490.1,1653 2494.1,1649 2502.1,1649 2506.1,1653 2506.1,1679 2510.1,1683 2518.1,1683 2522.1,1679 2522.1,1653 2526.1,1649 2534.1,1649 2538.1,1653 2538.1,1679 2542.1,1683 2550.1,1683 2554.1,1679 2554.1,1653 2558.1,1649 2566.1,1649 2570.1,1653 2570.1,1679 2574.1,1683 2584,1683 2589,1678 2589,1522.94 2610.69,1501.25 2639.73,1501.25 2643.24,1497.74
PSRAM_A12: U4.G3 U5.J12 | length 1400.5
  TOP w4: v6(2103,1461.47) 2103.63,1461.47 U4.G3@2118.34,1476.18
  L2_GND w3.5: v5(2834,1234) 2834,1245 2820,1259 2820,1270 2830,1280 2830,1317.84 v3(2838.73,1326.57)
  L3_SIG w4: v6(2103,1461.47) 2067.47,1497 2008,1497 1986,1475 1986,1384.58 2202.98,1167.6 2215.98,1167.6 2219.98,1171.6 2219.98,1181 2223.98,1185 2231.98,1185 2235.98,1181 2235.98,1171.6 2239.98,1167.6 2247.98,1167.6 2251.98,1171.6 2251.98,1181 2255.98,1185 2263.98,1185 2267.98,1181 2267.98,1171.6 2271.98,1167.6 2279.98,1167.6 2283.98,1171.6 2283.98,1181 2287.98,1185 2295.98,1185 2299.98,1181 2299.98,1171.6 2303.98,1167.6 2691.88,1167.6 2702.18,1177.9 2749.04,1177.9 2797.14,1226 2817.98,1226 2825.98,1234 v5(2834,1234)
PSRAM_A13: U4.G4 U5.J11 | length 1418.2
  TOP w4: v6(2133,1461) 2147.86,1475.86 U4.G4@2147.86,1476.18
  L2_GND w3.5: v5(2835,1265) 2835,1271.58 2851,1287.58 2851,1307.66 2848.66,1310 2848.66,1330.88 2838.73,1340.81 v3(2838.73,1346.26)
  L3_SIG w4: v6(2133,1461) 2133,1459.68 2120.32,1447 2096,1447 2058,1485 2015,1485 2000,1470 2000,1387.56 2190.56,1197 2315.55,1197 2319.55,1193 2319.55,1184 2323.55,1180 2331.55,1180 2335.55,1184 2335.55,1193 2339.55,1197 2347.55,1197 2351.55,1193 2351.55,1184 2355.55,1180 2363.55,1180 2367.55,1184 2367.55,1193 2371.55,1197 2379.55,1197 2383.55,1193 2383.55,1184 2387.55,1180 2395.55,1180 2399.55,1184 2399.55,1193 2403.55,1197 2411.55,1197 2415.55,1193 2415.55,1184 2419.55,1180 2427.55,1180 2431.55,1184 2431.55,1193 2435.55,1197 2443.55,1197 2447.55,1193 2447.55,1184 2451.55,1180 2687.3,1180 2697.2,1189.9 2744.06,1189.9 2792.16,1238 2803.98,1238 2830.98,1265 v5(2835,1265)
PSRAM_A14: U4.F3 U5.J10 | length 1593.2
  TOP w4: v6(2103,1550) 2103,1521.05 U4.F3@2118.34,1505.71
  L3_SIG w3.5: v4(2838.73,1365.94) 2838.73,1341.89 2890.7,1289.92 2890.7,1267.34 2877,1253.64 2877,1224.64 2860.86,1208.5
  L3_SIG w4: v6(2103,1550) 2097,1556 2016.06,1556 1950,1489.94 1950,1369.63 2191.63,1128 2703.22,1128 2717.12,1141.9 2800.76,1141.9 2848,1189.14 2848,1195.64 2860.86,1208.5
PSRAM_A15: U4.F4 U5.J9 | length 1432.8
  TOP w4: v6(2133,1491) 2147.71,1505.71 U4.F4@2147.86,1505.71
  L2_GND w3.5: v5(2816,1286) 2816,1295 2809.15,1301.85 2809.15,1350.36 2815,1356.21 2823.08,1356.21 2828.79,1361.92 2828.79,1375.69 v4(2838.73,1385.63)
  L3_SIG w4: v6(2133,1491) 2147,1477 2147,1455.2 2127.8,1436 2092,1436 2053,1475 2024,1475 2012,1463 2012,1392.54 2195.54,1209 2460.47,1209 2464.47,1205 2464.47,1196 2468.47,1192 2476.47,1192 2480.47,1196 2480.47,1205 2484.47,1209 2492.47,1209 2496.47,1205 2496.47,1196 2500.47,1192 2508.47,1192 2512.47,1196 2512.47,1205 2516.47,1209 2524.47,1209 2528.47,1205 2528.47,1196 2532.47,1192 2540.47,1192 2544.47,1196 2544.47,1205 2548.47,1209 2556.47,1209 2560.47,1205 2560.47,1196 2564.47,1192 2682.32,1192 2692.22,1201.9 2739.08,1201.9 2787.18,1250 2799,1250 2816,1267 v5(2816,1286)
PSRAM_A16: U4.E4 U5.K12 | length 1525.5
  TOP w4: U4.E4@2147.86,1535.24 2147.86,1535.14 v6(2162,1521)
  L3_SIG w3.5: v4(2819.04,1326.57) 2832.83,1326.57 2861,1298.4 2861,1226.34 2848,1213.34 2848,1212.98 2843.52,1208.5
  L3_SIG w4: v6(2162,1521) 2152,1521 2137,1536 2094,1536 2085,1545 2022.04,1545 1962,1484.96 1962,1374.61 2194.71,1141.9 2700.14,1141.9 2712.14,1153.9 2795.78,1153.9 2836,1194.12 2836,1200.98 2843.52,1208.5
PSRAM_A17: U4.D3 U5.K11 | length 1494.4
  TOP w4: U4.D3@2118.34,1564.76 2129.24,1564.76 2133,1561 v6(2133,1520)
  L3_SIG w3.5: v4(2819.04,1346.26) 2817,1346.26 2809.29,1338.55 2809.29,1322.53 2821.82,1310 2836.66,1310 2851,1295.66 2851,1232.96 2832.04,1214 2824.3,1214
  L3_SIG w4: v6(2133,1520) 2128,1515 2097,1515 2079,1533 2027.02,1533 1974,1479.98 1974,1379.6 2198,1155.6 2696.86,1155.6 2707.16,1165.9 2754.02,1165.9 2802.12,1214 2824.3,1214
PSRAM_A18: CN6.21 U4.H1 U5.K13 | length 2187.9
  TOP w5: CN6.21@1930.26,762.46 1967.44,762.46 v1(1990,739.9) ; U4.H1@2059.28,1446.65 2059.28,1422.72 v1(2240,1242) ; v4(2794,1262) 2809,1262 2819,1272 2819,1306.85 U5.K13@2819.04,1306.89
  L3_SIG w4: v1(2240,1242) 2210,1242 2205,1237 2205,1226 2210,1221 2266.69,1221 2270.69,1225 2270.69,1240.31 2275.38,1245 2282,1245 2286.69,1240.31 2286.69,1226 2291.69,1221 2328.69,1221 2333.69,1226 2333.69,1239.31 2338.38,1244 2345,1244 2349.69,1239.31 2349.69,1226 2354.69,1221 2360.69,1221 2365.69,1226 2365.69,1239.31 2370.38,1244 2377,1244 2381.69,1239.31 2381.69,1226 2386.69,1221 2394.56,1221 2399.56,1226 2399.56,1240 2403.56,1244 2411.56,1244 2415.56,1240 2415.56,1226 2420.56,1221 2427.11,1221 2432.11,1226 2432.11,1240 2436.11,1244 2444.11,1244 2448.11,1240 2448.11,1226 2453.11,1221 2459.11,1221 2464.11,1226 2464.11,1240 2468.11,1244 2476.11,1244 2480.11,1240 2480.11,1226 2485.11,1221 2491.11,1221 2496.11,1226 2496.11,1240 2500.11,1244 2508.11,1244 2512.11,1240 2512.11,1226 2517.11,1221 2524.51,1221 2529.51,1226 2529.51,1240 2533.51,1244 2541.51,1244 2545.51,1240 2545.51,1226 2550.51,1221 2558,1221 2563,1226 2563,1237 2568,1242 2574.07,1242 2579.07,1237 2579.07,1208.67 2583.74,1204 2590.33,1204 2595,1208.67 2595,1216 2600,1221 2607.07,1221 2611.07,1217 2611.07,1208 2615.07,1204 2623.07,1204 2627.07,1208 2627.07,1217.31 2631.76,1222 2638.38,1222 2643.07,1217.31 2643.07,1208 2647.07,1204 2655.07,1204 2659.07,1208 2659.07,1217 2663.07,1221 2696.27,1221 2700.27,1225 2700.27,1237.31 2704.96,1242 2711.58,1242 2716.27,1237.31 2716.27,1225 2720.27,1221 2731,1221 2736,1226 2736,1242 2756,1262 v4(2794,1262)
  BOTTOM w5: v1(1990,739.9) 2007.1,757 2107,757 2262,912 2262,983 2237,1008 2237,1239 v1(2240,1242)
PSRAM_NBL0: U4.A1 U5.A4 | length 1994.4
  TOP w4: v6(2044,1667.63) 2045,1667.63 U4.A1@2059.28,1653.35
  TOP w5: U5.A4@2996.21,1484.06 3019.56,1484.06 v6(3030.25,1494.75)
  BOTTOM w4: v6(2044,1667.63) 2044,1684 2049,1689 2087,1689 2091,1685
  BOTTOM w5: 2091,1685 2286,1685 2291,1680 2291,1651 2296,1646 2307.31,1646 2312.31,1651 2312.31,1717 2317.31,1722 2327.31,1722 2332.31,1717 2332.31,1579 2337.31,1574 2347.24,1574 2352.24,1579 2352.24,1717 2357.24,1722 2371,1722 2376,1717 2376,1679 2381,1674 2394,1674 2399,1679 2399,1717 2404,1722 2417,1722 2422,1717 2422,1667 2414,1659 2414,1579 2419,1574 2437,1574 2442,1579 2442,1681 2447,1686 2460,1686 2465,1681 2465,1637 2483,1619 2483,1572 2488,1567 2538,1567 2543,1562 2543,1504 2548,1499 2590.98,1499 2631.98,1458 2939.98,1458 2951.98,1470 3005.5,1470 v6(3030.25,1494.75)
PSRAM_NBL1: R13.1 U4.B2 U5.B4 | length 2152
  TOP w4: v6@2081,1710 2081,1704 2065,1688 2065,1670 2074,1661 2074,1638.63 U4.B2@2088.81,1623.82
  TOP w5: R13.1@2078.1,1815 2078.1,1715.9 v6(2081,1713) v6@2081,1710
  L2_GND w3.5: v3(2976.53,1484.06) 2989.06,1484.06 3026,1521 3035,1521 v5(3037,1523)
  L5_GND w3.5: v7(3014,1503) 3034,1523 v5(3037,1523)
  BOTTOM w5: v6(2081,1713) 2081,1715 2076,1720 2047,1720 2042,1725 2042,1767 2047,1772 2058.35,1772 2063.35,1767 2063.35,1747 2068.35,1742 2078.35,1742 2083.35,1747 2083.35,1767 2088.35,1772 2098.96,1772 2103.96,1767 2103.96,1735 2108.96,1730 2118.96,1730 2123.96,1735 2123.96,1767 2128.96,1772 2138.96,1772 2143.96,1767 2143.96,1738 2148.96,1733 2158.96,1733 2163.96,1738 2163.96,1767 2168.96,1772 2178.96,1772 2183.96,1767 2183.96,1731 2188.96,1726 2198.96,1726 2203.96,1731 2203.96,1767 2208.96,1772 2218.96,1772 2223.96,1767 2223.96,1710 2228.96,1705 2238.96,1705 2243.96,1710 2243.96,1767 2248.96,1772 2258.96,1772 2263.96,1767 2263.96,1710 2268.96,1705 2278.96,1705 2283.96,1710 2283.96,1767 2288.96,1772 2299,1772 2304,1767 2304,1746 2309,1741 2317.77,1741 2322.77,1746 2322.77,1766 2327.77,1771 2340,1771 2345,1766 2345,1745 2349,1741 2430,1741 2482,1689 2482,1645 2490,1637 2541,1637 2568,1610 2568,1543.2 2638.2,1473 2925,1473 2936,1484 2995,1484 v7(3014,1503)
PSRAM_NE: JP9.1 R12.2 U5.B7 | length 2026.8
  TOP w5: R12.2@2205,1815 2165,1855 JP9.1@2165,1960 2364,2159 2686,2159 2825,2020 2926.91,2020 3051.91,1895 3137.44,1895 3205,1827.44 3205,1488.78 3191.22,1475 3185,1475 3172,1462 v1(3170,1462)
  L3_SIG w3.5: v4(2976.53,1425) 2991.53,1440 3093,1440 3106,1427 3132,1427
  L3_SIG w4: 3132,1427 3137,1427 3170,1460 v1(3170,1462)
PSRAM_VDD: R13.2 R14.2 R15.1 R129.1 R130.1 SB12.2 | length 892.6
  TOP w20: 1880,1620 1875,1625 R129.1@1875,1670 R130.1@1875,1725 1875,1745 1895,1765 1910,1765 1960,1815 R13.2@2018.1,1815 2018.1,1838.1 v1(2055,1875) ; R15.1@2383.1,1685 R14.2@2383.1,1815 v1(2383.1,1875)
  BOTTOM w20: v1(2055,1875) v1(2383.1,1875)
PWR_ENN: R32.2 U6.28 U7.3 | length 1157.2
  TOP w5: v1(4260,1375) 4299.21,1335.79 U6.28@4395.36,1335.79
  TOP w20: v1(3425,1465) 3448.1,1488.1 R32.2@3460,1488.1 3465,1483.1 U7.3@3465,1401.4
  L3_SIG w5: v1(3425,1465) 4167.58,1465 4257.58,1375 v1(4260,1375)
QSPI_BK1_IO0: R8.1 U5.L5 | length 1425.8
  TOP w5: R8.1@3608.1,2160 3638.1,2130 v1(3640,2130)
  L2_GND w3.5: v5(2675,1500) 2680,1500 2704,1476 2704,1473 2721.2,1455.8 2768.5,1455.8 2769.86,1454.44 2789.44,1454.44 v3(2799.36,1464.36)
  L5_GND w3.5: v5(2675,1500) 2682,1507 v7@2682,1514.2
  L5_GND w5: v7@2682,1514.2 v7(2682,1518)
  BOTTOM w5: v7(2682,1518) 2734,1518 2748,1532 2969,1532 2983,1546 3056,1546 v1(3640,2130)
QSPI_BK1_IO1: R28.1 U5.K5 | length 1396.1
  TOP w5: v1(3481,1633) 3481,1629 R28.1@3510,1600
  L2_GND w3.5: v5(2750.63,1486.19) 2750.81,1486.19 2762.88,1474.12 2809.29,1474.12 v3(2819.04,1464.37)
  L5_GND w3.5: v5(2750.63,1486.19) 2751,1486.56 v7(2751,1514)
  BOTTOM w5: v7(2751,1514) 2972.2,1514 2988.2,1530 3076,1530 3084,1538 3197,1538 3209,1550 3209,1667 3223,1681 3307.58,1681 3312.58,1676 3312.58,1630 3317.58,1625 3327.58,1625 3332.58,1630 3332.58,1685 3337.58,1690 3349.54,1690 3354.54,1685 3354.54,1634 3359.54,1629 3369.54,1629 3374.54,1634 3374.54,1685 3379.54,1690 3389.54,1690 3394.54,1685 3394.54,1634 3399.54,1629 3409.54,1629 3414.54,1634 3414.54,1682 3419.54,1687 3476,1687 3481,1682 v1(3481,1633)
QSPI_BK1_IO2: R29.1 U5.L4 | length 1409.8
  TOP w5: R29.1@3560,1600 v1(3590,1630)
  L2_GND w3.5: v5(2723.25,1501.52) 2753.48,1501.52 2761.01,1493.99 2783.53,1493.99 2793.46,1484.06 v3(2799.36,1484.06)
  L5_GND w3.5: v5(2723.25,1501.52) 2723.25,1495.08 v7(2732.35,1485.98)
  BOTTOM w5: v7(2732.35,1485.98) 2732.98,1485.98 2747,1500 2981,1500 2995.25,1514.25 3076.25,1514.25 3084,1522 3210,1522 3228,1540 3228,1659 3233,1664 3243,1664 3248,1659 3248,1612 3253,1607 3263,1607 3268,1612 3268,1659 3273,1664 3283,1664 3288,1659 3288,1613 3293,1608 3513,1608 3518,1613 3518,1674 3523,1679 3585,1679 3590,1674 v1(3590,1630)
QSPI_BK1_IO3: R6.1 U5.M4 | length 1413.1
  TOP w5: R6.1@3508.1,2160 3535,2133.1 v1(3535,2130)
  L3_SIG w3.5: v5@2721.83,1517.73 2725.27,1517.73 2742,1501 2765,1501 2779.67,1486.33 v4(2779.67,1484.06)
  L3_SIG w4: v5(2715,1521) 2718.56,1521 v5@2721.83,1517.73
  L5_GND w5: v7(2714,1537) 2715,1536 v5(2715,1521)
  BOTTOM w5: v7(2714,1537) 2736,1537 2748.95,1549.95 2955,1549.95 2970.05,1565 3037,1565 3459,1987 3459,1994.74 3442.91,2010.83 3442.91,2017.91 3449.98,2024.98 3457.06,2024.98 3472.48,2009.56 3479.56,2009.56 3486.63,2016.63 3486.63,2023.71 3470.71,2039.63 3470.71,2046.71 3477.78,2053.78 3484.86,2053.78 3501.28,2037.36 3508.36,2037.36 3515.43,2044.43 3515.43,2051.51 3499.51,2067.43 3499.51,2074.51 3506.58,2081.58 3513.66,2081.58 3528.58,2066.66 3535.66,2066.66 3547.35,2078.35 3547.35,2085.43 3535,2097.78 v1(3535,2130)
